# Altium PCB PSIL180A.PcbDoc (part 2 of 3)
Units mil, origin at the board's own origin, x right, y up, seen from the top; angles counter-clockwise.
Board outline 4350 x 4350 mil, 4 copper layers (L1-Top Layer, L2-GND, L3-GND/SIG, L4-Bottom Layer), stack 60.02 mil thick; 134 components, 52 nets, 287 pads, 1110 vias.
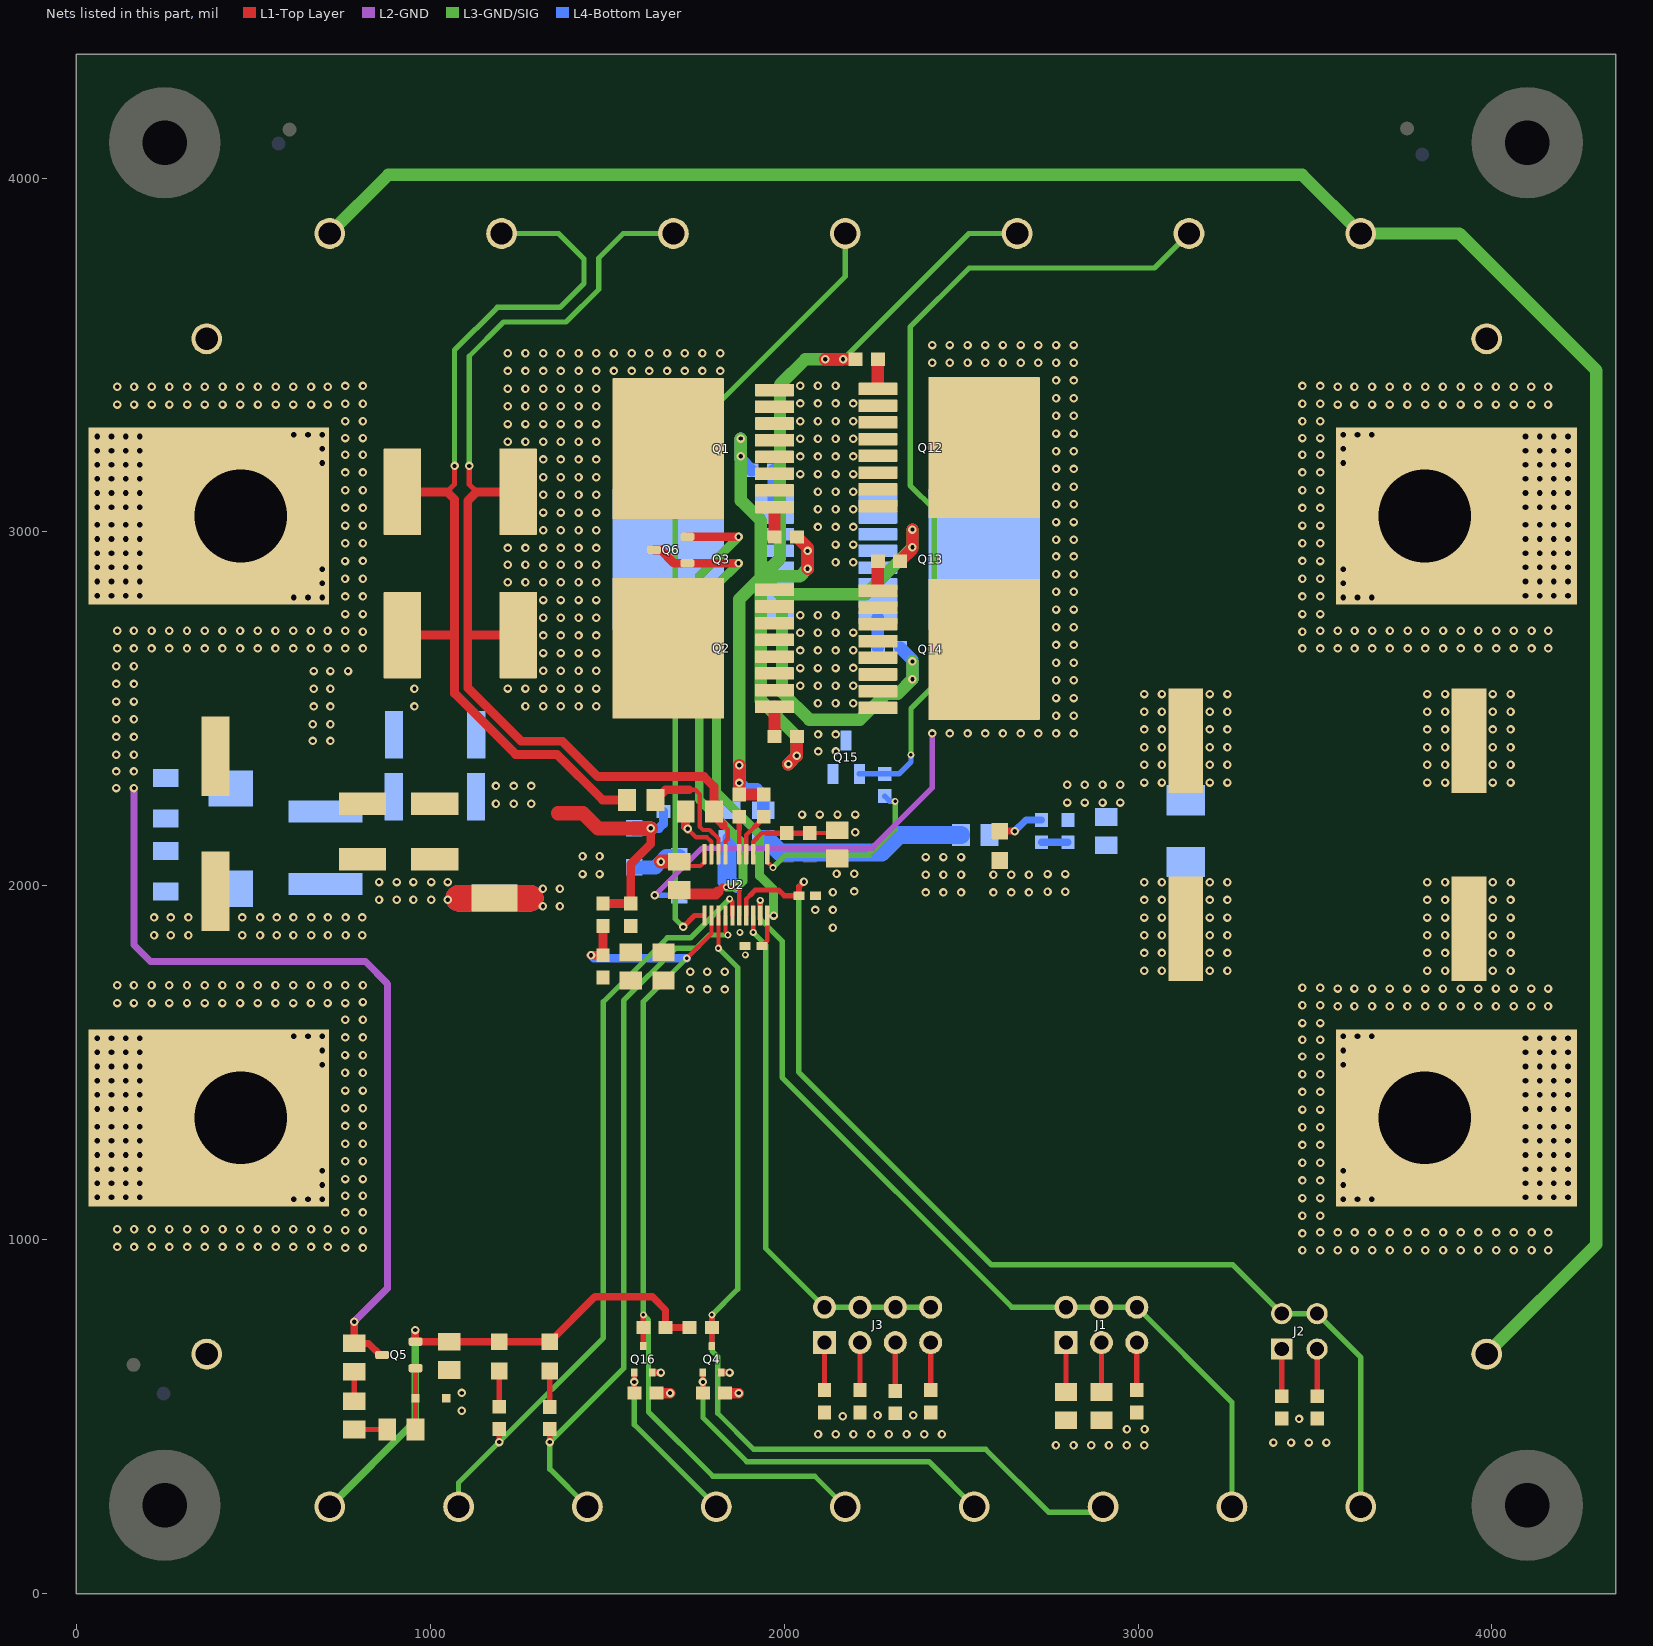
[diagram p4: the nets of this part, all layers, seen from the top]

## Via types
v1: diameter 24, hole 12, L1-Top Layer to L4-Bottom Layer, 863 vias
v2: diameter 32, hole 16, L1-Top Layer to L4-Bottom Layer, 232 vias
v3: diameter 20, hole 10, L1-Top Layer to L4-Bottom Layer, 15 vias

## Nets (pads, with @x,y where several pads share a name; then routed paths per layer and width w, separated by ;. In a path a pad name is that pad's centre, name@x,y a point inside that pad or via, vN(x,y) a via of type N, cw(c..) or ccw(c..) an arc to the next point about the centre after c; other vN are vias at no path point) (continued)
CS-: C5.1 C8.2 Q1.9 Q2.9 Q3.9 R1.2 R2.2 TP14.1 U2.17 | length 3008.8
  L1-Top Layer w12: 1827.86,2172.27 1840.84,2159.29 1840.84,2133.33 1834.21,2126.7 U2.17@1834.21,2089.62
  L1-Top Layer w15: v1(1110.64,3186.73) 1110.64,3134.74 1131.9,3113.48
  L1-Top Layer w25: R1.2@1248.56,2708.74 1106.23,2708.74 ; R2.2@1248.56,3113.48 1131.9,3113.48 1106.23,3087.8 1106.23,2708.74 ; 1827.86,2172.27 1801.93,2198.2 C8.2@1801.93,2210.36 1801.93,2280.55 1773.73,2308.75 1473.59,2308.75 1373.59,2408.75 1256.92,2408.75 1106.23,2559.44 1106.23,2708.74
  L3-GND/SIG w15: v1(1110.64,3186.73) 1110.64,3496.45 1207.29,3593.1 1384.08,3593.1 1476.34,3685.36 1476.34,3774.08 1545.6,3843.34 TP14.1@1687.36,3843.34
  other v1: 1269.37,2507.78 1319.37,2507.78 1369.37,2507.78 1419.37,2507.78 1469.37,2507.78 1219.37,2557.78 1269.37,2557.78 1319.37,2557.78 1369.37,2557.78 1419.37,2557.78 1469.37,2557.78 1319.37,2607.78 1369.37,2607.78 1419.37,2607.78 1469.37,2607.78 1319.37,2657.78 1369.37,2657.78 1419.37,2657.78 1469.37,2657.78 1319.37,2707.78 1369.37,2707.78 1419.37,2707.78 1469.37,2707.78 1319.37,2757.78 1369.37,2757.78 1419.37,2757.78 1469.37,2757.78 1319.37,2807.78 1369.37,2807.78 1419.37,2807.78 1469.37,2807.78 1219.37,2857.78 1269.37,2857.78 1319.37,2857.78 1369.37,2857.78 1419.37,2857.78 1469.37,2857.78 1219.37,2907.78 1269.37,2907.78 1319.37,2907.78 1369.37,2907.78 1419.37,2907.78 1469.37,2907.78 1219.37,2955.02 1269.37,2955.02 1319.37,2955.02 1369.37,2955.02 1419.37,2955.02 1469.37,2955.02 1319.37,3005.02 1369.37,3005.02 1419.37,3005.02 1469.37,3005.02 1319.37,3055.02 1369.37,3055.02 1419.37,3055.02 1469.37,3055.02 1319.37,3105.02 1369.37,3105.02 1419.37,3105.02 1469.37,3105.02 1319.37,3155.02 1369.37,3155.02 1419.37,3155.02 1469.37,3155.02 1319.37,3205.02 1369.37,3205.02 1419.37,3205.02 1469.37,3205.02 1219.37,3255.02 1269.37,3255.02 1319.37,3255.02 1369.37,3255.02 1419.37,3255.02 1469.37,3255.02 1219.37,3305.02 1269.37,3305.02 1319.37,3305.02 1369.37,3305.02 1419.37,3305.02 1469.37,3305.02 1219.37,3355.02 1269.37,3355.02 1319.37,3355.02 1369.37,3355.02 1419.37,3355.02 1469.37,3355.02 1219.37,3405.02 1269.37,3405.02 1319.37,3405.02 1369.37,3405.02 1419.37,3405.02 1469.37,3405.02 1219.37,3455.02 1269.37,3455.02 1319.37,3455.02 1369.37,3455.02 1419.37,3455.02 1469.37,3455.02 1519.37,3455.02 1569.37,3455.02 1619.37,3455.02 1669.37,3455.02 1719.37,3455.02 1769.37,3455.02 1819.37,3455.02 1219.37,3505.02 1269.37,3505.02 1319.37,3505.02 1369.37,3505.02 1419.37,3505.02 1469.37,3505.02 1519.37,3505.02 1569.37,3505.02 1619.37,3505.02 1669.37,3505.02 1719.37,3505.02 1769.37,3505.02 1819.37,3505.02
DIODE: C11.1 Q6.1 Q6.3 U2.10 | length 1453.7
  L1-Top Layer w12: C11.1@1937.29,1830.25 1952.32,1845.28 U2.10@1952.32,1916.4 1970.56,1916.4 v1(1970.64,1916.32)
  L1-Top Layer w25: Q6.3@1632.29,2949.3 1651.38,2949.3 1688.78,2911.9 Q6.1@1726.78,2911.9 v1(1871.45,2911.9)
  L3-GND/SIG w25: v1(1871.45,2911.9) 1809.04,2849.49 1809.04,2266.36 1930.86,2144.54 1930.86,2028.48 1970.64,1988.7 v1(1970.64,1916.32)
FLT_I/: R21.1 TP11.1 U2.5 | length 2160.5
  L1-Top Layer w12: v3(1846.12,1963.55) 1853.9,1955.77 U2.5@1853.9,1916.4 U2.5@1853.98,1916.32
  L1-Top Layer w15: v1(1195.28,428.8) R21.1@1195.28,465.57
  L3-GND/SIG w15: TP11.1@1080.41,246.13 1080.41,313.94 v1(1195.28,428.8) 1489.42,722.95 1489.42,1672.84 1669.91,1853.33 1735.9,1853.33 v3(1846.12,1963.55)
FLT_T/: R22.1 TP12.1 U2.4 | length 2026.1
  L1-Top Layer w12: U2.4@1834.21,1916.4 1834.21,1868.42 v3(1841.25,1861.38)
  L1-Top Layer w15: v1(1338.31,428.81) R22.1@1338.31,465.31
  L3-GND/SIG w15: TP12.1@1444.58,246.13 1338.31,352.4 v1(1338.31,428.81) 1546.65,637.14 1546.65,1676.19 1694.02,1823.56 1750.94,1823.56 1788.76,1861.38 v3(1841.25,1861.38)
G: R48.2 U2.11 | length 548.6
  L1-Top Layer w12: U2.11@1952.32,2089.62 1952.32,2068.05 v3(1968.71,2051.66)
  L3-GND/SIG w15: v3(1968.71,2051.66) 2003.94,2086.89 2239.34,2086.89 2313.96,2161.51 v3(2313.96,2239.07)
  L4-Bottom Layer w15: R48.2@2284.44,2253.59 2298.96,2239.07 v3(2313.96,2239.07)
GATE: R6.1 R8.1 R9.2 R10.2 R13.1 R15.2 R41.1 R43.1 R45.1 TP5.1 | length 5438.3
  L1-Top Layer w35: v1(1873.58,2341.17) v1(1873.58,2291.17) R10.2@1873.58,2258.49 R9.2@1942.83,2258.49 ; v1(2012.22,2344.32) v1(2035.95,2368.05) R8.1@2035.95,2422.22 ; R6.1@2036.58,2985.85 2066.58,2955.85 v1(2066.58,2946.41) v1(2066.58,2896.41) ; v1(2116.56,3487.9) v1(2166.56,3487.9) R41.1@2201.86,3487.9 ; R45.1@2327.84,2917.47 2362.84,2952.47 v1(2362.84,2956.91) v1(2362.84,3006.91)
  L3-GND/SIG w15: v1(2166.56,3487.9) 2522,3843.34 TP5.1@2658.48,3843.34
  L3-GND/SIG w35: v1(1873.58,2291.17) v1(1873.58,2341.17) 1873.58,2810.13 1934.41,2870.96 ; v1(1877.97,3263.93) v1(1877.97,3213.93) 1877.97,3088.61 1934.41,3032.17 1934.41,2870.96 ; v1(2012.22,2344.32) v1(2035.95,2368.05) 2035.95,2422.13 1934.41,2523.67 1934.41,2870.96 ; v1(2066.58,2946.41) v1(2066.58,2896.41) 2044.79,2874.62 1957.95,2874.62 1950.68,2881.89 ; v1(2166.56,3487.9) v1(2116.56,3487.9) 2059.81,3487.9 1988.53,3416.62 1988.53,2925.08 1948.01,2884.56 1950.68,2881.89 ; v1(2362.84,2634.28) v1(2362.84,2584.28) 2321.32,2542.75 2287.46,2542.75 2214.47,2469.76 2071.5,2469.76 1994.11,2547.15 1994.11,2818.44 1988.53,2824.02 ; v1(2362.84,3006.91) v1(2362.84,2956.91) 2229.95,2824.02 1988.53,2824.02 ; 1934.41,2870.96 1945.34,2881.89 1950.68,2881.89 ; 1950.68,2881.89 1950.68,2861.87 1988.53,2824.02
  L4-Bottom Layer w35: v1(1873.58,2341.17) v1(1873.58,2291.17) 1892.03,2272.72 1922.55,2272.72 1941.55,2253.72 R15.2@1941.55,2213.72 ; v1(1877.97,3263.93) v1(1877.97,3213.93) 1877.97,3204.49 R13.1@1907.97,3174.49 ; R43.1@2327.84,2673.72 2362.84,2638.72 v1(2362.84,2634.28) v1(2362.84,2584.28)
GND: C4.2 C5.2 C10.2 C11.2 C12.2 C13.2 C14.2 C19.2 C20.2 D6.2 NT1.2 NT2.2 Q4.2 Q6.2 Q16.2 R17.1 R23.1 R24.1 R25.1 R26.2 R27.1 R28.1 R29.1 R31.1 R44.1 R49.1 TP15.1 TP16.1 TP17.1 TP18.1 U2.6 | length 8905.7
  L1-Top Layer w10: NT1.2@1207.48,1965.73 NT1.2@1243.26,1965.73
  L1-Top Layer w12: v3(1836.81,1996.87) v3(1866.81,1996.87) 1873.58,1990.1 U2.6@1873.58,1916.4
  L1-Top Layer w20: Q16.2@1628.04,625.26 v1(1652.07,625.26) ; 1813.44,1983.56 1826.75,1996.87 v3(1836.81,1996.87) ; Q4.2@1821.91,625.26 v1(1845.95,625.26)
  L1-Top Layer w25: Q6.2@1726.78,2986.7 v1(1871.45,2986.7)
  L1-Top Layer w30: R49.1@1639.85,567.18 v1(1677.94,567.18) ; C4.2@1712.28,1988.68 1723.6,1977.36 1807.24,1977.36 1813.44,1983.56 ; R17.1@1833.72,567.18 v1(1871.81,567.18)
  L1-Top Layer w75: NT1.2@1243.26,1965.73 1282.15,1965.73
  L3-GND/SIG w25: v3(1836.81,1996.87) v3(1866.81,1996.87) 1884.27,2014.33 1884.27,2119.5 1760.44,2243.33 1760.44,2875.7 v1(1871.45,2986.7)
  L3-GND/SIG w35: TP15.1@716.24,3843.34 882.15,4009.25 3463.69,4009.25 TP16.1@3629.6,3843.34 3907.92,3843.34 4295.11,3456.15 4295.11,3367.83 4295.11,1090.71 4295.11,987.61 TP18.1@3985,677.5
  L4-Bottom Layer w10: NT2.2@1207.48,1965.73 NT2.2@1243.26,1965.73
  L4-Bottom Layer w20: C5.2@1845.82,2133.72 1822.42,2110.32 1822.42,2008.7 1835.53,1995.59 v3@1865.53,1995.59
  L4-Bottom Layer w35: 1845.82,2017.86 v3(1866.81,1996.87)
  L4-Bottom Layer w40: 1845.82,2017.86 C5.2@1845.82,2133.72
  L4-Bottom Layer w75: NT2.2@1243.26,1965.73 1282.15,1965.73
  other v1: 2767.97,419.6 2817.97,419.6 2867.97,419.6 2917.97,419.6 2967.97,419.6 3017.97,419.6 3382.5,427.23 3432.5,427.23 3482.5,427.23 3532.5,427.23 2096.16,451.1 2146.16,451.1 2196.16,451.1 2246.16,451.1 2296.16,451.1 2346.16,451.1 2396.16,451.1 2446.16,451.1 2968.56,464.87 3018.56,464.87 3455.14,494.16 2165.84,501.39 2264.27,504.24 2364.66,504.24 1089.29,517.55 1089.29,567.55 1735.28,1707.6 1783.28,1707.6 1832.28,1707.6 1735.28,1757.6 1783.28,1757.6 1832.28,1757.6 2138.18,1882.04 2088.18,1932.04 2138.18,1932.04 1318.88,1942.29 1366.88,1942.29 2400.18,1981.66 2450.18,1981.66 2500.18,1981.66 2138.18,1982.04 2198.22,1984.42 1318.88,1992.29 1366.88,1992.29 2400.18,2031.66 2450.18,2031.66 2500.18,2031.66 1430.6,2033.64 1478.6,2033.64 2148.22,2034.42 2198.22,2034.42 2400.18,2081.66 2450.18,2081.66 2500.18,2081.66 1430.6,2083.64 1478.6,2083.64
  other v3: 1890.55,1805.22 1875.14,1869.02
IMON: C10.1 J2.2 J2.4 TP10.1 U2.7 | length 3144.9
  L1-Top Layer w12: U2.7@1893.27,1916.4 1893.27,1963.07 1904.85,1974.64
  L1-Top Layer w15: 1904.85,1974.64 1918.56,1988.36 1984.81,1988.36 2000.75,1972.42 C10.1@2041.9,1972.38 2041.9,1997.53 v1(2056,2011.63)
  L3-GND/SIG w15: v1(2056,2011.63) 2041.2,1996.83 2041.2,1474.55 2586.36,929.39 3268.06,929.39 J2.2@3405.91,791.54 J2.4@3505.91,791.54 3629.6,667.85 TP10.1@3629.6,246.13
INP: Q4.3 R12.1 TP6.1 U2.3 | length 2783.7
  L1-Top Layer w12: v3(1814.53,1823.96) U2.3@1814.53,1916.4
  L1-Top Layer w15: Q4.3@1796.32,700.06 R12.1@1796.32,752.8 v3(1796.32,787.87)
  L3-GND/SIG w15: v3(1814.53,1823.96) 1869.26,1769.23 1869.26,860.8 v3(1796.32,787.87) 1796.32,686.31 1812.52,670.11 1812.52,510.17 1914.17,408.52 2569.63,408.52 2748,230.15 2885.28,230.15 2885.28,223.53 2910.62,223.53 TP6.1@2917.24,230.15
INP_G: Q16.3 R16.1 R31.2 R47.1 TP24.1 U2.2 | length 2633.2
  L1-Top Layer w12: v3(1725.16,1795.79) 1794.84,1865.47 U2.2@1794.84,1916.4
  L1-Top Layer w15: Q16.3@1602.45,700.06 R47.1@1602.45,752.8 v3(1602.45,787.87)
  L1-Top Layer w25: v1(1454.83,1804.23) R31.2@1488.81,1804.23 R16.1@1488.81,1886.9
  L3-GND/SIG w15: v3(1725.16,1795.79) 1602.45,1673.08 v3(1602.45,787.87) 1617.07,773.25 1617.07,514.09 1798.88,332.28 2086.77,332.28 TP24.1@2172.92,246.13
  L4-Bottom Layer w25: v1(1454.83,1804.23) 1463.26,1795.79 v3(1725.16,1795.79)
IWRN: J3.2 J3.4 J3.6 J3.8 U2.8 | length 1490.1
  L1-Top Layer w12: v3(1912.95,1868.63) U2.8@1912.95,1916.4
  L3-GND/SIG w15: v3(1912.95,1868.63) 1948.3,1833.28 1948.3,975.83 J3.2@2114.43,809.71 J3.4@2214.43,809.71 J3.6@2314.43,809.71 J3.8@2414.43,809.71
NetC1_2: C1.2 R3.2
NetC4_1: C4.1 D10.1 D11.1 U2.20 | length 317
  L1-Top Layer w12: C4.1@1703.7,2068.68 1716.35,2056.02 1763.54,2056.02 1775.16,2067.64 U2.20@1775.16,2089.62 U2.20@1775.16,2111.93
  L1-Top Layer w40: v1(1652.2,2068.68) C4.1@1703.7,2068.68
  L4-Bottom Layer w15: v1@1649.42,2065.9 v1(1652.2,2068.68)
  L4-Bottom Layer w40: D10.1@1577.02,2052.43 1635.95,2052.43 v1@1649.42,2065.9 ; v1(1652.2,2068.68) 1667.32,2083.8 D11.1@1703.7,2083.8
NetC8_1: C8.1 R14.2 U2.19 | length 220.3
  L1-Top Layer w12: v1(1727.78,2161.26) 1751.73,2137.31 1782.17,2137.31 1794.84,2124.64 U2.19@1794.84,2089.62
  L1-Top Layer w25: C8.1@1721.93,2210.36 1721.93,2167.11 v1(1727.78,2161.26)
  L4-Bottom Layer w25: R14.2@1721.93,2210.36 1721.93,2167.11 v1(1727.78,2161.26)
NetC9_1: C9.1 R15.1 | length 595.2
  L4-Bottom Layer w50: R15.1@1941.55,2133.72 1950.29,2133.72 1989.39,2094.62 2275.95,2094.62 2325.16,2143.83 C9.1@2500.16,2143.83
NetC13_1: C13.1 J1.1 | length 139.5
  L1-Top Layer w15: C13.1@2796.71,570.25 J1.1@2796.71,709.71
NetC14_1: C14.1 J1.3 | length 139.5
  L1-Top Layer w15: C14.1@2896.71,570.25 J1.3@2896.71,709.71
NetC19_1: C19.1 R42.1 R44.2 TP3.1 U2.1 | length 2240.6
  L1-Top Layer w12: 1769.23,1916.4 U2.1@1775.16,1916.4
  L1-Top Layer w15: v1(1715.21,1884.28) 1747.32,1916.4 1769.23,1916.4
  L3-GND/SIG w15: v1(1715.21,1884.28) 1692.6,1906.89 1692.6,3241.85 2172.92,3722.17 TP3.1@2172.92,3843.34
NetD3_1: D3.1 R30.1 | length 131.2
  L1-Top Layer w20: D3.1@2609.11,2154.79 v1(2651.88,2154.79)
  L4-Bottom Layer w20: v1(2651.88,2154.79) 2683.59,2186.5 R30.1@2727.18,2186.5
NetD4_2: D4.2 R21.2 | length 88.2
  L1-Top Layer w15: R21.2@1195.28,528.56 D4.2@1195.28,616.79
NetD5_2: D5.2 R22.2 | length 101.3
  L1-Top Layer w15: R22.2@1338.31,528.3 D5.2@1338.31,629.62
NetD6_1: D6.1 Q5.1 R20.1 | length 173.5
  L1-Top Layer w10: D6.1@958.78,557.51 958.98,557.71 D6.1@958.78,557.91
  L1-Top Layer w15: R20.1@958.78,464.21 D6.1@958.78,557.51 ; D6.1@958.78,557.91 Q5.1@958.78,637.5
NetJ1_5: J1.5 R23.2 | length 133.9
  L1-Top Layer w15: R23.2@2996.71,575.77 J1.5@2996.71,709.71
NetJ2_1: J2.1 R24.2 | length 133.4
  L1-Top Layer w15: R24.2@3406.32,558.13 J2.1@3406.32,691.54
NetJ2_3: J2.3 R25.2 | length 133.4
  L1-Top Layer w15: R25.2@3506.32,558.13 J2.3@3506.32,691.54
NetJ3_1: J3.1 R26.1 | length 133.9
  L1-Top Layer w15: R26.1@2114.43,575.77 J3.1@2114.43,709.71
NetJ3_3: J3.3 R27.2 | length 134
  L1-Top Layer w15: J3.3@2214.43,709.71 2214.43,575.81 R27.2@2214.47,575.77
NetJ3_5: J3.5 R28.2 | length 135.6
  L1-Top Layer w15: R28.2@2314.43,574.15 J3.5@2314.43,709.71
NetJ3_7: J3.7 R29.2 | length 133.9
  L1-Top Layer w15: R29.2@2414.43,575.77 J3.7@2414.43,709.71
NetQ1_1: Q1.1 R6.2 | length 83.8
  L1-Top Layer w35: R6.2@1972.96,2986.48 Q1.1@1972.96,3070.3
NetQ2_1: Q2.1 R8.2 | length 83.8
  L1-Top Layer w35: R8.2@1972.96,2422.22 Q2.1@1972.96,2506.04
NetQ3_1: Q3.1 R13.2 | length 83.8
  L4-Bottom Layer w35: Q3.1@1970.96,3090.67 R13.2@1970.96,3174.49
NetQ4_1: Q4.1 R17.2 TP7.1 | length 1029.8
  L1-Top Layer w15: R17.2@1770.73,567.18 v1(1770.73,598.74) Q4.1@1770.73,625.26
  L3-GND/SIG w15: v1(1770.73,598.74) 1770.73,497.45 1894.67,373.51 2409.71,373.51 TP7.1@2537.09,246.13
NetQ12_1: Q12.1 R41.2 | length 83.8
  L1-Top Layer w35: Q12.1@2264.85,3404.08 R41.2@2264.85,3487.9
NetQ13_1: Q13.1 R43.2 | length 83.8
  L4-Bottom Layer w35: R43.2@2264.85,2673.72 Q13.1@2264.85,2757.54
NetQ14_1: Q14.1 R45.2 | length 83.8
  L1-Top Layer w35: Q14.1@2264.85,2833.65 R45.2@2264.85,2917.47
NetQ15_1: Q15.1 R48.1 TP25.1 | length 2341.4
  L3-GND/SIG w15: v3(2358.5,2370.28) 2358.5,2501.16 2424.66,2567.32 2424.66,3063.44 2356.27,3131.83 2356.27,3578.86 2523.18,3745.77 3046.47,3745.77 TP25.1@3144.04,3843.34
  L4-Bottom Layer w15: Q15.1@2212.75,2316.58 R48.1@2284.44,2316.58 2324.95,2316.58 2358.5,2350.13 v3(2358.5,2370.28)
NetQ15_3: Q15.3 R4.2 R7.2
  other v1: 1185.98,2232.55 1235.98,2232.55 1285.98,2232.55 1185.98,2282.55 1235.98,2282.55 1285.98,2282.55 2096.41,2380.03 2146.41,2380.03 2095.95,2428.03 2145.95,2428.03
NetQ16_1: Q16.1 R49.2 TP26.1 | length 506.7
  L1-Top Layer w15: R49.2@1576.86,567.18 v1(1576.86,598.74) Q16.1@1576.86,625.26
  L3-GND/SIG w15: v1(1576.86,598.74) 1576.86,478.02 TP26.1@1808.75,246.13
NetR5_1: R5.1 U2.18 | length 345
  L1-Top Layer w12: 1731.13,2271.75 1748.99,2271.75 1762.05,2258.69 1762.05,2167.02 1770.86,2158.21 1790.11,2158.21 1814.53,2133.79 U2.18@1814.53,2089.62
  L1-Top Layer w25: R5.1@1636.51,2242.81 1665.45,2271.75 1731.13,2271.75
NetR9_1: R9.1 U2.14 | length 126.4
  L1-Top Layer w12: U2.14@1893.27,2089.62 1893.27,2143.93 1917.49,2168.16
  L1-Top Layer w15: 1917.49,2168.16 1942.83,2193.5 R9.1@1942.83,2195.5
NetR10_1: R10.1 U2.15 | length 105.9
  L1-Top Layer w12: U2.15@1873.58,2089.62 1873.58,2160.24
  L1-Top Layer w15: 1873.58,2160.24 R10.1@1873.58,2195.5
NetR11_1: R11.1 R30.2 | length 74.9
  L4-Bottom Layer w20: R30.2@2727.18,2123.5 R11.1@2802.09,2123.5
NetR18_1: R18.1 R19.2 | length 83.4
  L1-Top Layer w15: R19.2@785.75,544.21 R18.1@785.75,627.59
NetR19_1: R19.1 R20.2 | length 93
  L1-Top Layer w15: R19.1@785.75,464.21 R20.2@878.78,464.21
PGND: C2.2 C3.2 C9.2 C15.2 C16.2 C17.2 C18.2 C21.2 D1.2 D2.2 D3.2 NT1.1 NT2.1 R3.1 T3.1 T4.1 | length 149.3
  L1-Top Layer w10: NT1.1@1120.52,1965.73 NT1.1@1156.3,1965.73
  L1-Top Layer w75: 1081.63,1965.73 NT1.1@1120.52,1965.73
  L4-Bottom Layer w10: NT2.1@1120.52,1965.73 NT2.1@1156.3,1965.73
  L4-Bottom Layer w75: 1081.63,1965.73 NT2.1@1120.52,1965.73
  other v1: 3464.64,970.87 3514.64,970.87 3564.64,970.87 3611.89,970.87 3661.89,970.87 3711.89,970.87 3761.89,970.87 3811.89,970.87 3861.89,970.87 3911.89,970.87 3961.89,970.87 4011.89,970.87 4061.89,970.87 4111.89,970.87 4159.13,970.87 760.36,977.4 810.36,977.4 116.36,979.95 163.61,979.95 213.6,979.95 263.61,979.95 313.61,979.95 363.61,979.95 413.61,979.95 463.6,979.95 513.61,979.95 563.61,979.95 613.61,979.95 663.61,979.95 710.85,979.95 3464.64,1018.11 3514.64,1020.87 3564.64,1020.87 3611.89,1020.87 3661.89,1020.87 3711.89,1020.87 3761.89,1020.87 3811.89,1020.87 3861.89,1020.87 3911.89,1020.87 3961.89,1020.87 4011.89,1020.87 4061.89,1020.87 4111.89,1020.87 4159.13,1020.87 760.36,1027.4 810.36,1027.4 116.36,1029.95 163.61,1029.95 213.6,1029.95 263.61,1029.95 313.61,1029.95 363.61,1029.95 413.61,1029.95 463.6,1029.95 513.61,1029.95 563.61,1029.95 613.61,1029.95 663.61,1029.95 710.85,1029.95 3464.64,1068.11 3514.64,1068.11 760.36,1077.4 810.36,1077.4 3464.64,1118.11 3514.64,1118.11 760.36,1124.64 810.36,1124.64 3515.13,1167.91 3464.64,1168.11 760.36,1171.89 810.36,1171.89 3515.13,1217.91 3464.64,1218.11 760.36,1221.89 810.36,1221.89 3464.64,1268.11 3514.64,1268.11 760.36,1271.89 810.36,1271.89 3464.64,1318.11 3514.64,1318.11 760.36,1321.89 810.36,1321.89 3464.64,1368.11 3514.64,1368.11 760.36,1371.89 810.36,1371.89 3464.64,1418.11 3514.64,1418.11 760.36,1421.89 810.36,1421.89 3464.64,1468.11 3514.64,1468.11 810.36,1471.89 759.87,1472.09 3464.64,1518.11 3514.64,1518.11 810.36,1521.89 759.87,1522.09 3464.64,1565.36 3514.64,1565.36 760.36,1571.89 810.36,1571.89 3464.64,1612.6 3514.64,1612.6 760.36,1621.89 810.36,1621.89 3564.15,1660.05 3611.4,1660.05 3661.4,1660.05 3711.4,1660.05 3761.4,1660.05 3811.4,1660.05 3861.4,1660.05 3911.4,1660.05 3961.4,1660.05 4011.4,1660.05 4061.4,1660.05 4111.4,1660.05 4158.64,1660.05 3464.64,1662.6 3514.64,1662.6 115.87,1669.13 163.12,1669.13 213.12,1669.13 263.12,1669.13 313.11,1669.13 363.12,1669.13 413.12,1669.13 463.12,1669.13 513.12,1669.13 563.12,1669.13 613.12,1669.13 663.12,1669.13 710.36,1669.13 760.36,1669.13 810.36,1671.89 3564.15,1710.05 3611.4,1710.05 3661.4,1710.05 3711.4,1710.05 3761.4,1710.05 3811.4,1710.05 3861.4,1710.05 3911.4,1710.05 3961.4,1710.05 4011.4,1710.05 4061.4,1710.05 4111.4,1710.05 4158.64,1710.05 3464.64,1712.6 3514.64,1712.6 115.87,1719.13 163.12,1719.13 213.12,1719.13 263.12,1719.13 313.12,1719.13 363.12,1719.13 413.12,1719.13 463.12,1719.13 513.11,1719.13 563.12,1719.13 613.12,1719.13 663.12,1719.13 710.36,1719.13 760.36,1719.13 810.36,1719.13 3017.49,1760.61 3067.49,1760.61 3202.51,1760.61 3252.51,1760.61 3817.49,1760.61 3867.49,1760.61 4002.51,1760.61 4052.51,1760.61 3017.49,1810.61 3067.49,1810.61 3202.51,1810.61 3252.51,1810.61 3817.49,1810.61 3867.49,1810.61 4002.51,1810.61 4052.51,1810.61 220.09,1860.94 267.33,1860.94 317.33,1860.94 469.41,1860.94 519.41,1860.94 566.65,1860.94 613.89,1860.94 663.89,1860.94 711.14,1860.94 761.14,1860.94 808.38,1860.94 3017.49,1860.61 3067.49,1860.61 3202.51,1860.61 3252.51,1860.61 3817.49,1860.61 3867.49,1860.61 4002.51,1860.61 4052.51,1860.61 220.09,1910.94 267.33,1910.94 317.33,1910.94 469.41,1910.94 519.41,1910.94 566.65,1910.94 613.89,1910.94 663.89,1910.94 711.14,1910.94 761.14,1910.94 808.38,1910.94 3017.49,1910.61 3067.49,1910.61 3202.51,1910.61 3252.51,1910.61 3817.49,1910.61 3867.49,1910.61 4002.51,1910.61 4052.51,1910.61 855.63,1960.94 905.63,1960.94 952.87,1960.94 1002.87,1960.94 1050.11,1960.94 3017.49,1960.61 3067.49,1960.61 3202.51,1960.61 3252.51,1960.61 3817.49,1960.61 3867.49,1960.61 4002.51,1960.61 4052.51,1960.61 2591.7,1981.66 2641.7,1981.66 2691.7,1981.66 2744.36,1983.55 2794.36,1983.55 855.63,2010.94 905.63,2010.94 952.87,2010.94 1002.87,2010.94 1050.11,2010.94 3017.49,2010.61 3067.49,2010.61 3202.51,2010.61 3252.51,2010.61 3817.49,2010.61 3867.49,2010.61 4002.51,2010.61 4052.51,2010.61 2591.7,2031.66 2641.7,2031.66 2691.7,2031.66 2744.36,2033.55 2794.36,2033.55
  other v2: 615,1115 655,1115 695,1115 3580,1115 3620,1115 3660,1115 60,1120 100,1120 140,1120 180,1120 4095,1120 4135,1120 4175,1120 4215,1120 695,1155 3580,1155 60,1160 100,1160 140,1160 180,1160 4095,1160 4135,1160 4175,1160 4215,1160 695,1195 3580,1195 60,1200 100,1200 140,1200 180,1200 4095,1200 4135,1200 4175,1200 4215,1200 60,1240 100,1240 140,1240 180,1240 4095,1240 4135,1240 4175,1240 4215,1240 60,1280 100,1280 140,1280 180,1280 4095,1280 4135,1280 4175,1280 4215,1280 60,1320 100,1320 140,1320 180,1320 4095,1320 4135,1320 4175,1320 4215,1320 60,1370 100,1370 140,1370 180,1370 4095,1370 4135,1370 4175,1370 4215,1370 60,1410 100,1410 140,1410 180,1410 4095,1410 4135,1410 4175,1410 4215,1410 60,1450 100,1450 140,1450 180,1450 4095,1450 4135,1450 4175,1450 4215,1450 60,1490 100,1490 140,1490 180,1490 4095,1490 4135,1490 4175,1490 4215,1490 695,1495 3580,1495 60,1530 100,1530 140,1530 180,1530 4095,1530 4135,1530 4175,1530 4215,1530 695,1535 3580,1535 60,1570 100,1570 140,1570 180,1570 4095,1570 4135,1570 4175,1570 4215,1570 615,1575 655,1575 695,1575 3580,1575 3620,1575 3660,1575
SRC: C6.2 C7.2 C20.1 Q1.2 Q1.3 Q1.4 Q1.5 Q1.6 Q1.7 Q1.8 Q2.2 Q2.3 Q2.4 Q2.5 Q2.6 Q2.7 Q2.8 Q3.2 Q3.3 Q3.4 Q3.5 Q3.6 Q3.7 Q3.8 Q12.2 Q12.3 Q12.4 Q12.5 Q12.6 Q12.7 Q12.8 Q13.2 Q13.3 Q13.4 Q13.5 Q13.6 Q13.7 Q13.8 Q14.2 Q14.3 Q14.4 Q14.5 Q14.6 Q14.7 Q14.8 Q15.2 U2.13 | length 276.6
  L1-Top Layer w12: U2.13@1912.95,2089.62 1912.95,2125.02 1937.17,2149.24 1952.28,2149.24 ; C7.2@2072.41,2149.24 2142.07,2149.24 C20.1@2150.57,2157.74
  L1-Top Layer w15: 1952.28,2149.24 C7.2@2062.41,2149.24
  other v1: 2200.99,2151.77 2050.99,2201.77 2100.99,2201.77 2150.99,2201.77 2200.99,2201.77 2095.55,2515.84 2145.55,2515.84 2195.55,2515.84 2045.55,2565.67 2095.55,2565.67 2145.55,2565.67 2195.55,2565.84 2045.55,2615.51 2095.55,2615.51 2145.55,2615.51 2195.55,2615.84 2045.55,2665.35 2095.55,2665.35 2145.55,2665.35 2195.55,2665.84 2045.55,2715.19 2095.55,2715.19 2145.55,2715.19 2195.55,2715.84 2045.55,2765.02 2095.55,2765.02 2145.55,2765.02 2145.55,2914.54 2195.55,2914.54 2145.55,2964.38 2195.55,2964.38 2095.55,3014.21 2145.55,3014.21 2195.55,3014.21 2095.55,3064.05 2145.55,3064.05 2195.55,3064.05 2095.55,3113.89 2145.55,3113.89 2195.55,3113.89 2045.55,3163.73 2095.55,3163.73 2145.55,3163.73 2195.55,3163.73 2045.55,3213.57 2095.55,3213.57 2145.55,3213.57 2195.55,3213.57 2045.55,3263.4 2095.55,3263.4 2145.55,3263.4 2195.55,3263.4 2045.55,3313.24 2095.55,3313.24 2145.55,3313.24 2195.55,3313.24 2045.55,3363.08 2095.55,3363.08 2145.55,3363.08 2195.55,3363.08 2045.55,3412.92 2095.55,3412.92 2145.55,3412.92
TMR: J1.2 J1.4 J1.6 TP8.1 U2.9 | length 2516
  L1-Top Layer w12: U2.9@1932.64,1916.4 v3(1932.64,1958.93)
  L3-GND/SIG w15: v3(1932.64,1958.93) 1932.64,1906.54 1994.52,1844.66 1994.52,1458.75 2643.56,809.71 J1.2@2796.71,809.71 ; J1.2@2795.47,808.47 J1.2@2796.71,809.71 ; TP8.1@3265.43,246.13 3265.43,540.98 J1.6@2996.71,809.71 J1.4@2896.71,809.71 J1.2@2796.71,809.71
VAUX: C12.1 D4.1 D5.1 Q5.2 R12.2 R47.2 TP9.1 | length 1524.5
  L1-Top Layer w15: v1(958.02,745.23) v1@958.78,744.47
  L1-Top Layer w20: v1@958.78,744.47 Q5.2@958.78,712.3 C12.1@1054.26,712.3 D4.1@1195.28,712.3 D5.1@1338.31,712.3 1465.29,839.28 1628.51,839.28 1665.44,802.35 R47.2@1665.44,752.8 R12.2@1733.33,752.8
  L3-GND/SIG w20: TP9.1@716.24,246.13 958.02,487.91 v1(958.02,745.23)
VIN: C1.1 C16.1 C17.1 C18.1 C21.1 D1.1 D10.2 Q5.3 R1.1 R2.1 R4.1 R5.2 R7.1 R14.1 R16.2 R18.2 R42.2 T1.1 TP1.1 TP13.1 | length 5717.5
  L1-Top Layer w15: 1047.62,3113.48 1068.96,3134.81 v1(1068.96,3186.73)
  L1-Top Layer w20: v1(785.75,768.96) R18.2@785.75,707.59 826.28,707.59 858.97,674.9 Q5.3@864.29,674.9
  L1-Top Layer w25: R1.1@921.79,2708.74 1069.23,2708.74 ; R2.1@921.79,3113.48 1047.62,3113.48 1069.23,3091.87 1069.23,2708.74 ; R16.2@1488.81,1949.9 R42.2@1566.93,1949.9 1566.93,2061.93 1623.41,2118.41 v1(1623.41,2162.67) ; R5.2@1556.51,2242.81 1487.2,2242.81 1358.26,2371.75 1241.59,2371.75 1069.23,2544.11 1069.23,2708.74
  L1-Top Layer w40: 1361.29,2205.44 1432.04,2205.44 1474.81,2162.67 v1(1623.41,2162.67)
  L2-GND w20: v1(163.12,2276.38) 163.12,1833.09 210.13,1786.07 817.45,1786.07 880.03,1723.5 880.03,863.24 v1(785.75,768.96)
  L3-GND/SIG w15: v1(1068.96,3186.73) 1068.96,3513.72 1190.02,3634.78 1366.81,3634.78 1434.66,3702.63 1434.66,3771.86 1363.18,3843.34 TP13.1@1201.8,3843.34
  L4-Bottom Layer w25: v1(1623.41,2162.67) 1646.46,2162.67 1658.94,2175.15 R14.1@1658.94,2210.36
  L4-Bottom Layer w40: D10.2@1577.02,2162.67 v1(1623.41,2162.67)
  other v1: 113.12,2276.38 113.12,2323.62 163.12,2323.62 113.12,2370.87 163.12,2370.87 668.26,2409.78 718.26,2409.78 113.12,2420.87 163.12,2420.87 668.26,2457.02 718.26,2457.02 113.12,2470.87 163.12,2470.87 671.01,2507.02 718.26,2507.02 955.79,2507.02 113.12,2520.87 163.12,2520.87 671.01,2557.02 718.26,2557.02 955.79,2557.02 113.12,2570.87 163.12,2570.87 671.01,2607.02 718.26,2607.02 768.26,2607.02 113.12,2620.87 163.12,2620.87 115.87,2670.87 163.12,2670.87 213.12,2670.87 263.12,2670.87 313.12,2670.87 363.12,2670.87 413.12,2670.87 463.12,2670.87 513.12,2670.87 563.12,2670.87 613.12,2670.87 663.12,2670.87 710.36,2670.87 760.36,2670.87 810.36,2670.87 810.36,2718.11 115.87,2720.87 163.12,2720.87 213.12,2720.87 263.12,2720.87 313.12,2720.87 363.12,2720.87 413.12,2720.87 463.12,2720.87 513.12,2720.87 563.12,2720.87 613.12,2720.87 663.12,2720.87 710.36,2720.87 760.36,2720.87 760.36,2768.11 810.36,2768.11 760.36,2818.11 810.36,2818.11 759.87,2867.91 810.36,2868.11 759.87,2917.91 810.36,2918.11 760.36,2968.11 810.36,2968.11 760.36,3018.11 810.36,3018.11 760.36,3068.11 810.36,3068.11 760.36,3118.11 810.36,3118.11 760.36,3168.11 810.36,3168.11 760.36,3218.11 810.36,3218.11 760.36,3265.36 810.36,3265.36 760.36,3312.6 810.36,3312.6 116.36,3360.05 163.61,3360.05 213.6,3360.05 263.61,3360.05 313.61,3360.05 363.61,3360.05 413.61,3360.05 463.6,3360.05 513.61,3360.05 563.61,3360.05 613.61,3360.05 663.61,3360.05 710.85,3360.05 760.36,3362.6 810.36,3362.6 116.36,3410.05 163.61,3410.05 213.61,3410.05 263.61,3410.05 313.61,3410.05 363.61,3410.05 413.61,3410.05 463.61,3410.05 513.61,3410.05 563.61,3410.05 613.61,3410.05 663.61,3410.05 710.85,3410.05 760.36,3412.6 810.36,3412.6
  other v2: 615,2815 655,2815 695,2815 60,2820 100,2820 140,2820 180,2820 695,2855 60,2860 100,2860 140,2860 180,2860 695,2895 60,2900 100,2900 140,2900 180,2900 60,2940 100,2940 140,2940 180,2940 60,2980 100,2980 140,2980 180,2980 60,3020 100,3020 140,3020 180,3020 60,3070 100,3070 140,3070 180,3070 60,3110 100,3110 140,3110 180,3110 60,3150 100,3150 140,3150 180,3150 60,3190 100,3190 140,3190 180,3190 695,3195 60,3230 100,3230 140,3230 180,3230 695,3235 60,3270 100,3270 140,3270 180,3270 615,3275 655,3275 695,3275
VOUT: C2.1 C3.1 C15.1 D2.1 D11.2 Q12.9 Q13.9 Q14.9 R11.2 T2.1 TP2.1 | length 1132.2
  L2-GND w15: v1(1634.88,1973.56) 1768.22,2106.9 2248.74,2106.9 2418.44,2276.59 v1(2418.44,2430.86)
  L4-Bottom Layer w15: v1(1634.88,1973.56) D11.2@1703.7,1973.56
  other v1: 2799.82,2235.68 2849.82,2235.68 2899.82,2235.68 2949.82,2235.68 2799.82,2285.68 2849.82,2285.68 2899.82,2285.68 2949.82,2285.68 3017.49,2292.11 3067.49,2292.11 3202.51,2292.11 3252.51,2292.11 3817.49,2292.11 3867.49,2292.11 4002.51,2292.11 4052.51,2292.11 3017.49,2342.11 3067.49,2342.11 3202.51,2342.11 3252.51,2342.11 3817.49,2342.11 3867.49,2342.11 4002.51,2342.11 4052.51,2342.11 3017.49,2392.11 3067.49,2392.11 3202.51,2392.11 3252.51,2392.11 3817.49,2392.11 3867.49,2392.11 4002.51,2392.11 4052.51,2392.11 2468.44,2430.86 2518.44,2430.86 2568.44,2430.86 2618.44,2430.86 2668.44,2430.86 2718.44,2430.86 2768.44,2430.86 2818.44,2430.86 3017.49,2442.11 3067.49,2442.11 3202.51,2442.11 3252.51,2442.11 3817.49,2442.11 3867.49,2442.11 4002.51,2442.11 4052.51,2442.11 2768.44,2480.86 2818.44,2480.86 3017.49,2492.11 3067.49,2492.11 3202.51,2492.11 3252.51,2492.11 3817.49,2492.11 3867.49,2492.11 4002.51,2492.11 4052.51,2492.11 2768.44,2530.86 2818.44,2530.86 3017.49,2542.11 3067.49,2542.11 3202.51,2542.11 3252.51,2542.11 3817.49,2542.11 3867.49,2542.11 4002.51,2542.11 4052.51,2542.11 2768.44,2580.86 2818.44,2580.86 2768.44,2630.86 2818.44,2630.86 3464.64,2670.87 3514.64,2670.87 3564.64,2670.87 3611.89,2670.87 3661.89,2670.87 3711.89,2670.87 3761.89,2670.87 3811.89,2670.87 3861.89,2670.87 3911.89,2670.87 3961.89,2670.87 4011.89,2670.87 4061.89,2670.87 4111.89,2670.87 4159.13,2670.87 2768.44,2680.86 2818.44,2680.86 3464.64,2718.11 3514.64,2720.87 3564.64,2720.87 3611.89,2720.87 3661.89,2720.87 3711.89,2720.87 3761.89,2720.87 3811.89,2720.87 3861.89,2720.87 3911.89,2720.87 3961.89,2720.87 4011.89,2720.87 4061.89,2720.87 4111.89,2720.87 4159.13,2720.87 2768.44,2730.86 2818.44,2730.86 3464.64,2768.11 3514.64,2768.11 2768.44,2780.86 2818.44,2780.86 3464.64,2818.11 3514.64,2818.11 2768.44,2830.86 2818.44,2830.86 3515.13,2867.91 3464.64,2868.11 2768.44,2880.86 2818.44,2880.86 3515.13,2917.91 3464.64,2918.11 2768.44,2930.86 2818.44,2930.86 3464.64,2968.11 3514.64,2968.11 2768.44,2978.1 2818.44,2978.1 3464.64,3018.11 3514.64,3018.11 2768.44,3028.1 2818.44,3028.1 3464.64,3068.11 3514.64,3068.11 2768.44,3078.1 2818.44,3078.1 3464.64,3118.11 3514.64,3118.11 2768.44,3128.1 2818.44,3128.1 3464.64,3168.11 3514.64,3168.11 2768.44,3178.1 2818.44,3178.1 3464.64,3218.11 3514.64,3218.11 2768.44,3228.1 2818.44,3228.1 3464.64,3265.36 3514.64,3265.36 2768.44,3278.1 2818.44,3278.1 3464.64,3312.6 3514.64,3312.6 2768.44,3328.1 2818.44,3328.1 3564.15,3360.05 3611.4,3360.05 3661.4,3360.05 3711.4,3360.05 3761.4,3360.05 3811.4,3360.05 3861.4,3360.05 3911.4,3360.05 3961.4,3360.05 4011.4,3360.05 4061.4,3360.05 4111.4,3360.05 4158.64,3360.05 3464.64,3362.6 3514.64,3362.6 2768.44,3378.1 2818.44,3378.1 3564.15,3410.05 3611.4,3410.05 3661.4,3410.05 3711.4,3410.05 3761.4,3410.05 3811.4,3410.05 3861.4,3410.05 3911.4,3410.05 3961.4,3410.05 4011.4,3410.05 4061.4,3410.05 4111.4,3410.05 4158.64,3410.05 3464.64,3412.6 3514.64,3412.6 2768.44,3428.1 2818.44,3428.1 2418.44,3478.1 2468.44,3478.1 2518.44,3478.1 2568.44,3478.1 2618.44,3478.1 2668.44,3478.1 2718.44,3478.1 2768.44,3478.1 2818.44,3478.1 2418.44,3528.1 2468.44,3528.1 2518.44,3528.1 2568.44,3528.1 2618.44,3528.1 2668.44,3528.1 2718.44,3528.1 2768.44,3528.1 2818.44,3528.1
  other v2: 3580,2815 3620,2815 3660,2815 4095,2820 4135,2820 4175,2820 4215,2820 3580,2855 4095,2860 4135,2860 4175,2860 4215,2860 3580,2895 4095,2900 4135,2900 4175,2900 4215,2900 4095,2940 4135,2940 4175,2940 4215,2940 4095,2980 4135,2980 4175,2980 4215,2980 4095,3020 4135,3020 4175,3020 4215,3020 4095,3070 4135,3070 4175,3070 4215,3070 4095,3110 4135,3110 4175,3110 4215,3110 4095,3150 4135,3150 4175,3150 4215,3150 4095,3190 4135,3190 4175,3190 4215,3190 3580,3195 4095,3230 4135,3230 4175,3230 4215,3230 3580,3235 4095,3270 4135,3270 4175,3270 4215,3270 3580,3275 3620,3275 3660,3275
pads on no net: FID1.1 FID2.1 FID3.1 FID4.1 FID5.1 FID6.1 H1.1 H2.1 H3.1 H4.1 H5.0 H6.0 H7.0 H8.0 SH-J1.0 SH-J2.0 SH-J3.0

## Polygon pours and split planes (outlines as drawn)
GND on L1-Top Layer "L1-Top Layer-GND 1" (solid, remove dead copper, pour order 174): 1346.11,1619.69 1229.29,1736.51 1229.29,1908.33 1208.39,1929.23 1208.39,2001.67 1229.29,2022.57 1229.29,2054.59 1250.77,2076.07 1334.85,2076.07 1380.41,2121.63 1505.92,2121.63 1527.77,2099.78 1527.77,2012.14 1506.51,1990.88 1468.6,1990.88 1426.65,1948.93 1426.65,1792.19 1445.47,1773.37 1773.35,1773.37 1857.4,1857.42 1857.4,1869.81 1867.72,1880.13 1867.72,1945.17 1868.92,1946.37 1878.27,1946.37 1879.45,1945.19 1879.45,1882.84 1890.75,1871.54 1890.75,1858.72 1907.72,1841.75 1907.72,1809.56 1917.38,1799.9 1997.16,1799.9 2070.65,1873.39 2070.65,1983.63 2109.23,2022.21 2109.23,2094.57 2122.19,2107.53 2200.9,2107.53 2273.6,2180.23 2429.34,2180.23 2506.7,2180.23 2514.74,2172.19 2514.74,1788.89 2345.54,1619.69
VOUT on L1-Top Layer "L1-Top Layer-VOUT 1" (solid, remove dead copper, pour order 154): 2385.81,2391.68 2399.36,2405.23 2399.36,3532.47 2449.22,3582.33 2764.55,3582.33 2851.07,3668.85 2851.07,4246.52 2916.44,4311.89 4236.52,4311.89 4316.07,4232.34 4316.07,2277.74 4247.12,2208.79 2407.71,2208.79 2385.81,2230.69
PGND on L1-Top Layer "L1-Top Layer-PGND 1" (solid, remove dead copper, pour order 110): 1065.97,2151.09 1142.08,2074.98 1142.08,2017.14 1156.54,2002.68 1156.54,1929 1142.08,1914.54 1142.08,1737.49 1319.43,1560.14 2360.99,1560.14 2571.47,1770.62 2571.47,2085.34 2589.51,2103.38 2650.5,2103.38 2727.64,2180.52 4244.3,2180.52 4316.91,2107.91 4316.91,979.19 4267.68,929.96 131.98,929.96 33.33,1028.61 33.33,2058.45 125.97,2151.09
no net on L1-Top Layer "L1-Top Layer-No Net 1" (solid, remove dead copper, pour order 152): 1680.21,1996.21
SRC on L1-Top Layer "L1-Top Layer-VIN" (solid, remove dead copper, pour order 150): 2068.88,2328.84 1982.43,2242.39 1982.43,2175.16 1969.98,2162.71 1939.44,2162.71 1907.05,2130.32 1907.05,2061.94 1908.02,2060.97 1917.85,2060.97 1918.83,2061.95 1918.83,2122.32 1925.8,2129.29 2196.24,2129.29 2328.92,2261.97 2328.92,2795.22 2319.31,2804.83 2206.2,2804.83 2195.96,2815.07 2195.96,2858.72 2228.34,2891.1 2228.34,2940.01 2234.5,2946.17 2310.18,2946.17 2328.92,2964.91 2328.92,3365.58 2319.39,3375.11 2202.67,3375.11 2189.81,3387.97 2189.81,3433.19 2180.25,3442.75 1927.58,3442.75 1910.92,3426.1 1910.92,3103.16 1914.25,3099.83 2030.84,3099.83 2044.11,3086.56 2044.11,3039.64 2099.95,2984.21 2099.95,2876.67 2085.64,2862.36 1920.43,2862.36 1910.92,2852.85 1910.92,2542.38 1918.44,2534.96 2032.45,2534.96 2068.88,2498.53
CS- on L1-Top Layer "L1-Top Layer-CS-" (solid, remove dead copper, pour order 6): 92.7,3645.08 1054.75,3645.08 1192.82,3507.01 1192.82,2557.57 1295.25,2455.14 1395.43,2455.14 1504.24,2346.33 1775.24,2346.33 1830.64,2401.73 1830.64,2869.19 1822.14,2877.69 1614.05,2877.69 1598.92,2892.82 1598.92,3003.71 1615.58,3020.37 1819.04,3020.37 1830.44,3031.77 1830.44,3436.48 2003.28,3609.32 2753.48,3609.32 2824.14,3679.98 2824.14,4238.51 2747.98,4314.67 121.63,4314.67 33.33,4226.37 33.33,3704.45
VIN on L1-Top Layer "L1-Top Layer-VIN" (solid, remove dead copper, pour order 68): 1366.18,2156.61 1309.88,2100.31 1148.76,2100.31 1071.83,2177.24 131.69,2177.24 33.33,2275.6 33.33,3543.4 92.44,3602.51 897.93,3602.51 977.67,3522.77 977.67,3240.15 977.67,2898.61 977.67,2523.06 1163.02,2337.71 1163.02,2334.61 1338.08,2334.61 1405.43,2267.26 1405.43,2236.48 1416.87,2225.04 1416.87,2186.17 1407.94,2177.24 1386.58,2177.24
GND on L1-Top Layer "L1-Top Layer-GND" (solid, remove dead copper, pour order 112): 4274.08,893.13 4318.92,848.29 4318.92,100.57 4256.14,37.79 1954.09,37.79 135.88,37.79 47.55,126.12 47.55,816.08 124.6,893.13
NetQ15_3 on L4-Bottom Layer "L4-Bottom Layer-NetQ15_3" (solid, remove dead copper, pour order 202): 1207.7,2506.12 1322.27,2391.55 1322.27,2207.68 1292.05,2177.46 1107.55,2177.46 1098.41,2186.6 1098.41,2487.94 1116.59,2506.12
NetQ15_3 on L4-Bottom Layer "L4-Bottom Layer-NetQ15_3 1" (solid, remove dead copper, pour order 200): 2195.27,2443.16 2203.73,2434.7 2203.73,2375.16 2195.07,2366.5 2137.87,2366.5 2090.04,2366.5 2083.59,2372.95 2083.59,2434.72 2092.03,2443.16
NetC1_2 on L4-Bottom Layer "L4-Bottom Layer-NetC1_2" (solid, remove dead copper, pour order 198): 297.28,2218.64 209,2218.64 193.9,2203.54 193.9,2084.96 207.04,2071.82 297.84,2071.82 307.71,2081.69 307.71,2208.21
VOUT on L4-Bottom Layer "L1-Top Layer-VOUT 1" (solid, remove dead copper, pour order 168): 2772.76,2211.25 2763.07,2220.94 2680.04,2220.94 2667.58,2208.79 2411.06,2208.79 2383.81,2236.04 2383.81,2389.68 2399.36,2405.23 2399.36,2407.05 2399.36,3532.47 2449.22,3582.33 2764.55,3582.33 2851.07,3668.85 2851.07,4246.52 2916.44,4311.89 4236.52,4311.89 4316.07,4232.34 4316.07,2231.51 4247.3,2162.74 2785.34,2162.74 2772.76,2175.32
SRC on L4-Bottom Layer "L1-Top Layer-VIN" (solid, remove dead copper, pour order 166): 2218.25,2489.39 2188.09,2459.23 2083.1,2459.23 2067.3,2443.14 2067.3,2367.92 2086.02,2349.2 2153.7,2349.2 2161.61,2341.29 2161.61,2293.72 2221.28,2234.05 2221.28,2153.33 2206.79,2138.84 2044.18,2138.84 2006.9,2176.12 2006.9,2238.16 1910.92,2334.14 1910.92,3050.77 1918.97,3058.82 2031.13,3058.82 2038.79,3066.48 2038.79,3121.07 2017.31,3142.55 2017.31,3197.14 2002.96,3211.49 1936.64,3211.49 1910.92,3237.21 1910.92,3426.1 1927.58,3442.75 2298.85,3442.75 2328.92,3412.68 2328.92,2795.22 2320.58,2786.88 2204.11,2786.88 2196.86,2779.63 2196.86,2737.72 2218.25,2716.33
CS- on L4-Bottom Layer "L1-Top Layer-CS-" (solid, remove dead copper, pour order 164): 1830.44,2287.52 1879.56,2238.4 1879.56,2190.51 1877.23,2188.18 1768.78,2188.18 1756.71,2200.25 1756.71,2242.97 1712.5,2287.23 1462.5,2287.23 1148.84,2600.89 1148.84,3342.31 1148.84,3550.99 1054.75,3645.08 92.7,3645.08 33.33,3704.45 33.33,4226.37 121.63,4314.67 2747.98,4314.67 2824.14,4238.51 2824.14,3679.98 2753.48,3609.32 2003.28,3609.32 1830.44,3436.48
PGND on L4-Bottom Layer "L1-Top Layer-PGND 1" (solid, remove dead copper, pour order 162): 1142.08,2074.98 1142.08,2017.14 1156.54,2002.68 1156.54,1929 1142.08,1914.54 1142.08,1737.51 1319.45,1560.14 2360.99,1560.14 2571.47,1770.62 2571.47,2091.3 2554.71,2108.06 2554.71,2175.75 2561.1,2182.14 2616.56,2182.14 2627.39,2171.31 2627.39,2133.98 2676.12,2085.25 2824.35,2085.25 2883.48,2144.38 4279.97,2144.85 4316.91,2107.91 4316.91,979.19 4267.68,929.96 131.98,929.96 33.33,1028.61 33.33,1811.52 33.33,1949.74 120.91,2037.32 309.57,2037.32 423.34,2151.09 1065.97,2151.09
VIN on L4-Bottom Layer "L1-Top Layer-VIN" (solid, remove dead copper, pour order 160): 1033.92,2225.61 979.31,2171 388.69,2171 302.29,2257.4 97.74,2257.4 33.33,2321.81 33.33,2908.51 33.33,3543.4 92.44,3602.51 897.93,3602.51 1033.92,3466.52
